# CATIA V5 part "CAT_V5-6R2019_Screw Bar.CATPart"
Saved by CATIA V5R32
Part number: Screw Bar
Bounding box of the stored display mesh (mm): x -3 to 3, y -52 to 52, z -2.853 to 2.853
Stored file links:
  D:\PROJECTS\Project 2022\CATIA V5 6R 2022\Resources\Tutorial Files\c13_catia_v5_6r2022_tut\c13tut2\Bench vice\CAT_V5-6R2019_Screw Bar.CATPart
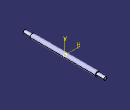
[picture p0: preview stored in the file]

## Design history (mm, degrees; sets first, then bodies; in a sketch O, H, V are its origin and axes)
Body1 (main body)
  Sketch1 on zx-plane, origin (0, 0, 0), H (-1, 0, 0), V (0, 0, 1)
    circle A1 centre (0, 0) radius 2
    radius A1 = 2
  Sketch2 on zx-plane, origin (0, 0, 0), H (-1, 0, 0), V (0, 0, 1)
    circle A1 centre (0, 0) radius 3
    radius A1 = 3
  Pad1: profile Sketch1, direction (0, 1, 0), length 52, mirrored extent
  Pad2: profile Sketch2, direction (0, 1, 0), length 42, mirrored extent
